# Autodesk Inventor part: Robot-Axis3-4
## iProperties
Shininess: 21.0
Length Units: 11269
Angle Units: 11279
Time Units: 11290
Mass Units: 11283
Length Display Precision: 3
Angle Display Precision: 2
Created: 2001-08
Part Number: Robot-Axis3-4
Document SubType Name: ﾓﾃﾞﾘﾝｸﾞ
Designer: Administrator
Density: 1 g/cm^3
Density: 0.0
Volumn: 0.0
Area: 0.0
PropertySet Name: Model Information
Control State: 0
Master: False
Checked Out: False
Author: Administrator
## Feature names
1. 押し出し1 [Extrusion]
2. 押し出し2 [Extrusion]
3. Mirror1
4. 押し出し3 [Extrusion]
5. 押し出し4 [Extrusion]
6. Chamfer1 [Fillet]
7. Chamfer2 [Fillet]
8. Chamfer3 [Fillet]
9. Shell1
10. Hole1
11. Hole2
